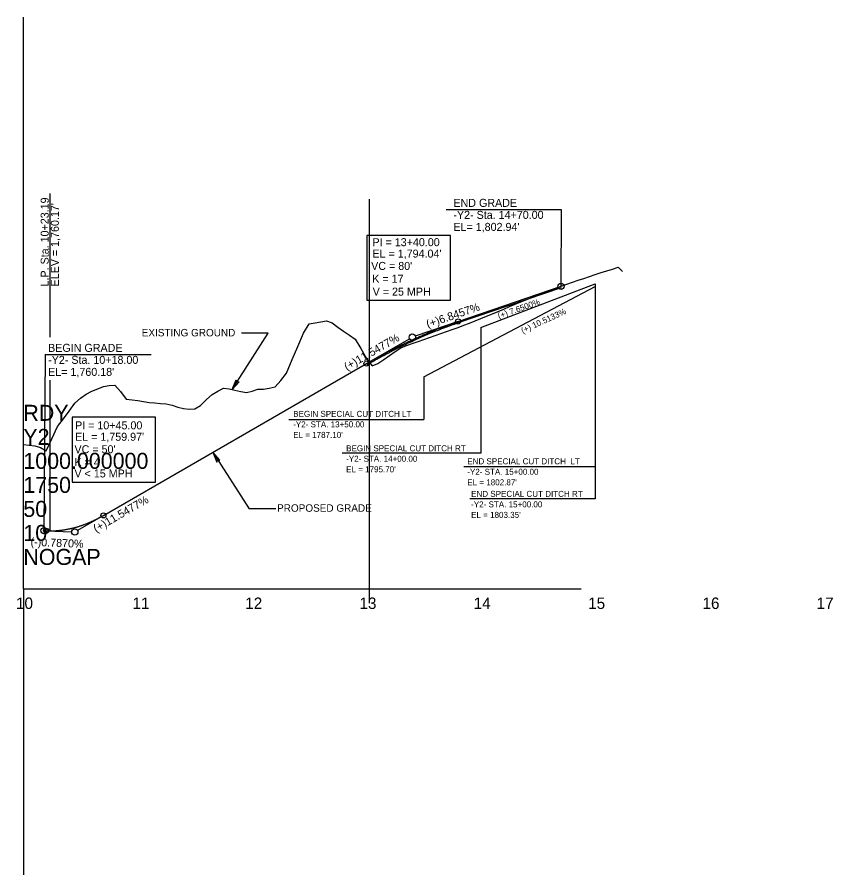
# Model space of a CAD drawing. Extents: x 498575 to 532350, y 405181 to 484585.
# Drawn here: x 505851 to 506564, y 477111 to 477861 of the extents above; entities that cross this region are included whole.
import ezdxf

# ---------------------------------------------------------------- set-up
doc = ezdxf.new("R2010")
doc.units = 0
for name, color, linetype in [('Exist Profile Cell', 7, 'Continuous'), ('Exist Vertical Profile Ground Line', 7, 'Continuous'), ('Exist Vertical Profile Horizontal Axis Label Major', 7, 'Continuous'), ('Prop Grid Mask', 7, 'Continuous'), ('Prop PFL Text', 7, 'Continuous'), ('Prop Vertical Profile Curve Label', 7, 'Continuous'), ('Prop Vertical Profile Ditch Grade Left', 7, 'Continuous'), ('Prop Vertical Profile Ditch Grade Left Label', 7, 'Continuous'), ('Prop Vertical Profile Ditch Grade Right', 7, 'Continuous'), ('Prop Vertical Profile Ditch Grade Right Label', 7, 'Continuous'), ('Prop Vertical Profile Grade', 7, 'Continuous'), ('Prop Vertical Profile Grade Label', 7, 'Continuous'), ('Prop Vertical Profile Strip Grade', 7, 'Continuous'), ('Prop VPI Label', 7, 'Continuous'), ('Scratch_Level_5', 7, 'Continuous')]:
    doc.layers.add(name, color=color, linetype=linetype)

msp = doc.modelspace()

# ---------------------------------------------------------------- linework, layer by layer
at = {"layer": 'Exist Profile Cell'}
for q in [(505856.74, 477861.02), (506344.49, 477361.02), (505856.74, 477111.02)]:
    msp.add_line((505856.74, 477361.02), q, dxfattribs=at)
at = {"layer": 'Exist Vertical Profile Ground Line'}
for points in [[(506356.74, 477636.03), (506361.74, 477637.63), (506366.74, 477639.21), (506371.74, 477640.79), (506376.74, 477642.37), (506380.47, 477638.73)], [(505856.74, 477487.2), (505861.74, 477486.72), (505866.74, 477486.2), (505871.74, 477484.69), (505876.74, 477481.78), (505881.74, 477492.4), (505886.74, 477503.05), (505891.74, 477509.77), (505896.74, 477516.58), (505901.74, 477523.51), (505906.74, 477527.75), (505911.74, 477531.21), (505916.74, 477533.97), (505921.74, 477535.93), (505926.74, 477538.01), (505931.74, 477538.9), (505936.74, 477539.29), (505941.74, 477533.54), (505946.74, 477527.05), (505951.74, 477526.46), (505956.74, 477525.73), (505961.74, 477524.93), (505966.74, 477524.16), (505971.74, 477523.74), (505976.74, 477523.25), (505981.74, 477522.75), (505986.74, 477521.74), (505991.74, 477519.93), (505996.74, 477518.82), (506001.74, 477518.37), (506006.74, 477518.42), (506011.74, 477521.54), (506016.74, 477526.58), (506021.74, 477531.14), (506026.74, 477533.82), (506031.74, 477536.73), (506036.74, 477535.94), (506041.74, 477534.82), (506046.74, 477533.7), (506051.74, 477532.88), (506056.74, 477534.07), (506061.74, 477535.61), (506066.74, 477535.83), (506071.74, 477536.5), (506076.74, 477537.76), (506081.74, 477543.15), (506086.74, 477549.85), (506091.74, 477561.59), (506096.74, 477573.09), (506101.74, 477584.59), (506106.74, 477592.74), (506111.74, 477593.6), (506116.74, 477594.66), (506121.74, 477595.56), (506126.74, 477593.59), (506131.74, 477589.91), (506136.74, 477586.43), (506141.74, 477582.94), (506146.74, 477579.45), (506151.74, 477571.2), (506156.74, 477562.67), (506161.74, 477556.19), (506166.74, 477558.13), (506171.74, 477561.66), (506176.74, 477565.14), (506181.74, 477568.58), (506186.74, 477571.92), (506191.74, 477573.94), (506196.74, 477575.67), (506201.74, 477577.42), (506206.74, 477579.19), (506211.74, 477580.95), (506216.74, 477582.66), (506221.74, 477584.39), (506226.74, 477586.15), (506231.74, 477587.94), (506236.74, 477589.73), (506241.74, 477591.6), (506246.74, 477593.52), (506251.74, 477595.51), (506256.74, 477597.53), (506261.74, 477599.56), (506266.74, 477601.57), (506271.74, 477603.69), (506276.74, 477605.78), (506281.74, 477607.86), (506286.74, 477609.96), (506291.74, 477612.05), (506296.74, 477614.14), (506301.74, 477616.17), (506306.74, 477618.15), (506311.74, 477620.14), (506316.74, 477622.06), (506321.74, 477623.88), (506326.74, 477625.7), (506331.74, 477627.51), (506336.74, 477629.22), (506341.74, 477630.92), (506346.74, 477632.63), (506351.74, 477634.33), (506356.74, 477636.03)]]:
    msp.add_lwpolyline(points, dxfattribs=at)
at = {"layer": 'Prop Grid Mask'}
for points in [[(506157.01, 477613.43), (506230.02, 477613.43), (506230.02, 477670.21), (506157.01, 477670.21)], [(505899.37, 477454.47), (505972.38, 477454.47), (505972.38, 477511.25), (505899.37, 477511.25)]]:
    msp.add_lwpolyline(points, close=True, dxfattribs=at)
at = {"layer": 'Prop PFL Text'}
for p, q in [((506039.24, 477535.38), (506070.77, 477584.57)), ((506070.77, 477584.57), (506047.35, 477584.57)), ((506022.36, 477480.52), (506054.09, 477431.03)), ((506077.51, 477431.03), (506054.09, 477431.03))]:
    msp.add_line(p, q, dxfattribs=at)
for points in [[(506045.35, 477542.17), (506039.24, 477535.38), (506042.71, 477543.89), (506043.45, 477542.06)], [(506028.47, 477473.74), (506022.36, 477480.52), (506025.83, 477472.01), (506026.57, 477473.84)]]:
    msp.add_lwpolyline(points, close=True, dxfattribs=at)
at = {"layer": 'Prop Vertical Profile Curve Label'}
for centre in [(506236.74, 477594.9), (506156.74, 477558.11), (505926.74, 477425.31), (505876.74, 477411.86)]:
    msp.add_circle(centre, 2.25, dxfattribs=at)
at = {"layer": 'Prop Vertical Profile Ditch Grade Left'}
msp.add_lwpolyline([(506206.74, 477546.52), (506356.74, 477625.37)], dxfattribs=at)
at = {"layer": 'Prop Vertical Profile Ditch Grade Left Label'}
for p, q in [((506356.74, 477625.37), (506356.74, 477467.89)), ((506206.74, 477546.52), (506206.74, 477509.32)), ((506088.72, 477509.32), (506206.74, 477509.32)), ((506356.74, 477467.89), (506241.69, 477467.89))]:
    msp.add_line(p, q, dxfattribs=at)
at = {"layer": 'Prop Vertical Profile Ditch Grade Right'}
msp.add_lwpolyline([(506256.74, 477589.52), (506356.74, 477627.77)], dxfattribs=at)
at = {"layer": 'Prop Vertical Profile Ditch Grade Right Label'}
for p, q in [((506356.74, 477627.77), (506356.74, 477439.72)), ((506256.74, 477589.52), (506256.74, 477479.8)), ((506256.74, 477479.8), (506135.37, 477479.8)), ((506356.74, 477439.72), (506246.98, 477439.72))]:
    msp.add_line(p, q, dxfattribs=at)
at = {"layer": 'Prop Vertical Profile Grade'}
for p, q in [((506236.74, 477594.9), (506326.74, 477625.7)), ((505926.74, 477425.31), (506156.74, 477558.11)), ((505874.74, 477411.94), (505876.74, 477411.86))]:
    msp.add_line(p, q, dxfattribs=at)
for points in [[(506156.74, 477558.11), (506158.34, 477559.03), (506159.94, 477559.94), (506161.54, 477560.85), (506163.14, 477561.75), (506164.74, 477562.64), (506166.34, 477563.52), (506167.94, 477564.39), (506169.54, 477565.26), (506171.14, 477566.12), (506172.74, 477566.97), (506174.34, 477567.82), (506175.94, 477568.66), (506177.54, 477569.49), (506179.14, 477570.31), (506180.74, 477571.12), (506182.34, 477571.93), (506183.94, 477572.73), (506185.54, 477573.52), (506187.14, 477574.31), (506188.74, 477575.08), (506190.34, 477575.85), (506191.94, 477576.61), (506193.54, 477577.37), (506195.14, 477578.12), (506196.74, 477578.86), (506198.34, 477579.59), (506199.94, 477580.31), (506201.54, 477581.03), (506203.14, 477581.74), (506204.74, 477582.44), (506206.34, 477583.13), (506207.94, 477583.82), (506209.54, 477584.5), (506211.14, 477585.17), (506212.74, 477585.84), (506214.34, 477586.49), (506215.94, 477587.14), (506217.54, 477587.78), (506219.14, 477588.42), (506220.74, 477589.05), (506222.34, 477589.66), (506223.94, 477590.28), (506225.54, 477590.88), (506227.14, 477591.48), (506228.74, 477592.07), (506230.34, 477592.65), (506231.94, 477593.22), (506233.54, 477593.79), (506235.14, 477594.35), (506236.74, 477594.9)], [(505876.74, 477411.86), (505877.74, 477411.83), (505878.74, 477411.81), (505879.74, 477411.8), (505880.74, 477411.8), (505881.74, 477411.82), (505882.74, 477411.85), (505883.74, 477411.89), (505884.74, 477411.94), (505885.74, 477412.01), (505886.74, 477412.09), (505887.74, 477412.18), (505888.74, 477412.28), (505889.74, 477412.39), (505890.74, 477412.52), (505891.74, 477412.66), (505892.74, 477412.81), (505893.74, 477412.98), (505894.74, 477413.15), (505895.74, 477413.34), (505896.74, 477413.54), (505897.74, 477413.76), (505898.74, 477413.98), (505899.74, 477414.22), (505900.74, 477414.47), (505901.74, 477414.73), (505902.74, 477415.01), (505903.74, 477415.3), (505904.74, 477415.6), (505905.74, 477415.91), (505906.74, 477416.23), (505907.74, 477416.57), (505908.74, 477416.92), (505909.74, 477417.28), (505910.74, 477417.65), (505911.74, 477418.04), (505912.74, 477418.44), (505913.74, 477418.85), (505914.74, 477419.27), (505915.74, 477419.71), (505916.74, 477420.16), (505917.74, 477420.62), (505918.74, 477421.09), (505919.74, 477421.57), (505920.74, 477422.07), (505921.74, 477422.58), (505922.74, 477423.1), (505923.74, 477423.64), (505924.74, 477424.18), (505925.74, 477424.74), (505926.74, 477425.31)]]:
    msp.add_spline(points, degree=3, dxfattribs=at)
at = {"layer": 'Prop Vertical Profile Strip Grade'}
for p, q in [((505879.93, 477706.93), (505879.93, 477581.31)), ((505879.93, 477543.72), (505879.93, 477411.8))]:
    msp.add_line(p, q, dxfattribs=at)
at = {"layer": 'Prop VPI Label'}
for p, q in [((506226.22, 477692.81), (506327, 477692.81)), ((506327, 477692.81), (506326.73, 477625.7)), ((506236.74, 477594.9), (506199.34, 477582.1)), ((506156.74, 477558.11), (506194.36, 477579.83)), ((505875.77, 477565.99), (505874.74, 477411.94)), ((505875.77, 477565.99), (505968.51, 477565.99)), ((505926.74, 477425.31), (505904.12, 477412.25)), ((505876.74, 477411.86), (505898.99, 477410.99))]:
    msp.add_line(p, q, dxfattribs=at)
for centre in [(506326.74, 477625.7), (506196.74, 477581.21), (505874.74, 477411.94), (505901.74, 477410.88)]:
    msp.add_circle(centre, 2.75, dxfattribs=at)
at = {"layer": 'Scratch_Level_5'}
for p, q in [((506159.32, 477348.52), (506159.32, 477701.73)), ((506237.08, 477593.91), (506327.08, 477624.72))]:
    msp.add_line(p, q, dxfattribs=at)
msp.add_open_spline([(506157.26, 477557.21), (506157.66, 477557.44), (506158.16, 477557.72), (506158.68, 477558.02), (506158.8, 477558.1), (506158.85, 477558.12), (506158.88, 477558.14), (506158.95, 477558.18), (506159, 477558.21), (506159.25, 477558.35), (506159.65, 477558.58), (506160.04, 477558.81), (506160.34, 477558.98), (506160.44, 477559.03), (506160.64, 477559.15), (506161.14, 477559.43), (506163.24, 477560.61), (506165.24, 477561.73), (506170.06, 477564.37), (506173.29, 477566.1), (506183.05, 477571.18), (506189.63, 477574.42), (506202.94, 477580.58), (506209.67, 477583.49), (506219.87, 477587.6), (506223.29, 477588.93), (506228.44, 477590.85), (506230.16, 477591.48), (506232.32, 477592.25), (506232.97, 477592.48), (506233.62, 477592.71), (506233.94, 477592.82), (506234.05, 477592.86), (506234.26, 477592.94), (506234.37, 477592.98), (506234.7, 477593.09), (506234.91, 477593.17), (506235.24, 477593.28), (506235.34, 477593.32), (506235.51, 477593.37), (506235.56, 477593.39), (506235.67, 477593.43), (506236.16, 477593.6), (506236.65, 477593.76), (506237.08, 477593.91)], degree=3, dxfattribs=at)

# ---------------------------------------------------------------- texts
at = {"layer": 'Exist Profile Cell'}
for s, p in [('RDY', (505856.74, 477508.02)), ('Y2', (505856.74, 477487.02)), ('1000.000000', (505856.74, 477466.02)), ('1750', (505856.74, 477445.02)), ('50', (505856.74, 477424.02)), ('10', (505856.74, 477403.02)), ('NOGAP', (505856.74, 477382.02))]:
    msp.add_text(s, height=14, dxfattribs=at).set_placement(p)
at = {"layer": 'Exist Vertical Profile Horizontal Axis Label Major'}
for s, p in [('10', (505850.32, 477343.52)), ('11', (505952.16, 477343.52)), ('12', (506050.71, 477343.52)), ('13', (506150.55, 477343.52)), ('14', (506250.39, 477343.52)), ('15', (506350.48, 477343.52)), ('16', (506450.42, 477343.52)), ('17', (506550.16, 477343.52))]:
    msp.add_text(s, height=10, dxfattribs=at).set_placement(p)
at = {"layer": 'Prop PFL Text'}
for s, p in [('EXISTING GROUND', (505960.24, 477581.87)), ('PROPOSED GRADE', (506078.56, 477428.51))]:
    msp.add_text(s, height=6.5157, dxfattribs=at).set_placement(p)
at = {"layer": 'Prop Vertical Profile Curve Label'}
for s, p in [("VC = 80'", (506160.79, 477639.99)), ('K = 17', (506161.77, 477628.8)), ('V = 25 MPH ', (506162.12, 477617.5)), ("VC = 50'", (505901.44, 477479.66)), ('K = 4', (505901.44, 477468.4)), ('V < 15 MPH ', (505901.44, 477458.53))]:
    msp.add_text(s, height=7, dxfattribs=at).set_placement(p)
at = {"layer": 'Prop Vertical Profile Ditch Grade Left Label'}
for s, rotation, p in [('(+) 10.5133%', 24.50461, (506293.28, 477584.3)), ('BEGIN SPECIAL CUT DITCH LT', 360, (506092.63, 477511.49)), ('-Y2- STA. 13+50.00', 360, (506092.63, 477502.3)), ("EL = 1787.10'", 360, (506092.63, 477493.11)), ('END SPECIAL CUT DITCH  LT', 360, (506244.82, 477470.02)), ('-Y2- STA. 15+00.00', 360, (506244.82, 477460.83)), ("EL = 1802.87'", 360, (506244.82, 477451.64))]:
    msp.add_text(s, height=5.25, rotation=rotation, dxfattribs=at).set_placement(p)
at = {"layer": 'Prop Vertical Profile Ditch Grade Right Label'}
for s, rotation, p in [('(+) 7.6500%', 19.3589, (506272.55, 477597.14)), ('BEGIN SPECIAL CUT DITCH RT', 360, (506138.93, 477481.4)), ('-Y2- STA. 14+00.00', 360, (506138.93, 477472.22)), ("EL = 1795.70'", 360, (506138.93, 477463.03)), ('END SPECIAL CUT DITCH RT', 360, (506248.18, 477441.54)), ('-Y2- STA. 15+00.00', 360, (506248.18, 477432.35)), ("EL = 1803.35'", 360, (506248.18, 477423.16))]:
    msp.add_text(s, height=5.25, rotation=rotation, dxfattribs=at).set_placement(p)
at = {"layer": 'Prop Vertical Profile Grade Label'}
for s, rotation, p in [('(+)6.8457%', 18.89536, (506210.36, 477589.04)), ('(+)11.5477%', 30.00153, (506139.6, 477551.68)), ('(+)11.5477%', 30.00153, (505920.38, 477410.09)), ('(-)0.7870%', 357.74647, (505862.94, 477398.75))]:
    msp.add_text(s, height=7, rotation=rotation, dxfattribs=at).set_placement(p)
at = {"layer": 'Prop Vertical Profile Strip Grade'}
for s, p in [('L.P. Sta. 10+23.19', (505878.91, 477625.54)), ("ELEV = 1,760.17'", (505887.78, 477625.54))]:
    msp.add_text(s, height=7, rotation=90, dxfattribs=at).set_placement(p)
at = {"layer": 'Prop VPI Label'}
for s, p in [('END GRADE', (506232.68, 477695.12)), ('-Y2- Sta. 14+70.00', (506232.68, 477684.62)), ("EL= 1,802.94'", (506232.68, 477674.12)), ('PI = 13+40.00', (506161.9, 477660.75)), ("EL = 1,794.04'", (506161.9, 477650.75)), ('BEGIN GRADE', (505878.42, 477568.34)), ('-Y2- Sta. 10+18.00', (505878.42, 477557.84)), ("EL= 1,760.18'", (505878.42, 477547.34)), ('PI = 10+45.00', (505901.95, 477500.59)), ("EL = 1,759.97'", (505901.95, 477490.59))]:
    msp.add_text(s, height=7, dxfattribs=at).set_placement(p)

doc.saveas('drawing.dxf')
